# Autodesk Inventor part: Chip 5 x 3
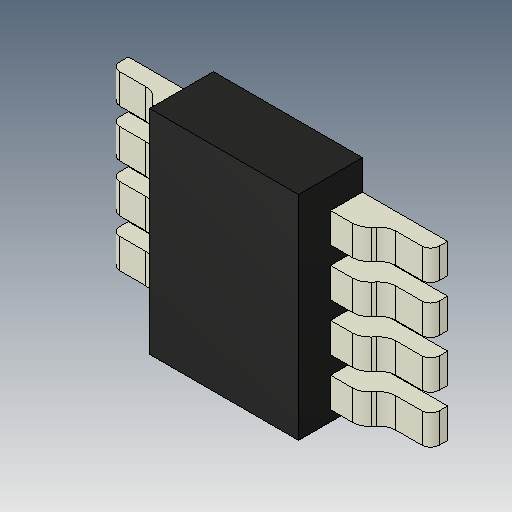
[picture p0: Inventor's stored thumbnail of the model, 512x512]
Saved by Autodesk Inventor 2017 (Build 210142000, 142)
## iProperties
Created: 2005-12
Part Number: Chip 5 x 3
Material: Generic
Document SubType Name: Modeling
Designer: DanielSeverino
Density: 1 g/cm^3
Appearance: Default
Author: DanielSeverino
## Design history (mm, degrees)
feature "Solid1"
body "Solid2"
